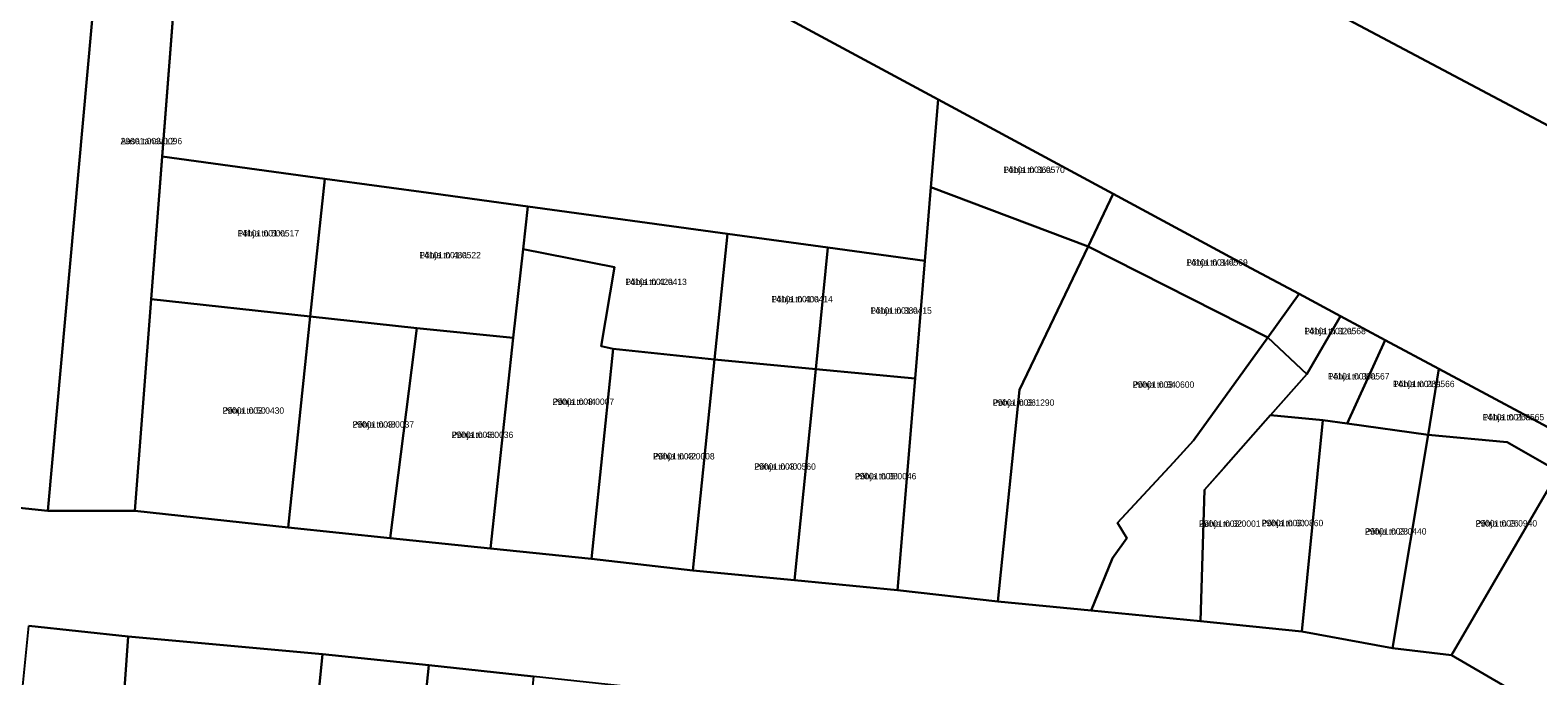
# Model space of a CAD drawing. Extents: x 566437 to 602312, y 6556921 to 6586574.
# Drawn here: x 574798.1 to 575153.3, y 6578752.1 to 6578904.2 of the extents above; entities that cross this region are included whole.
import ezdxf

# ---------------------------------------------------------------- set-up
doc = ezdxf.new("R2010")
doc.units = 0
for name, color, linetype in [('L_AADRESS', 7, 'Continuous'), ('PIIR', 7, 'Continuous'), ('TUNNUS', 7, 'Continuous')]:
    doc.layers.add(name, color=color, linetype=linetype)

msp = doc.modelspace()

# ---------------------------------------------------------------- linework, layer by layer
at = {"layer": 'PIIR'}
for points in [[(575406, 6578752.29), (575349.07, 6578781.07), (575166.28, 6578876.15), (574957.16, 6578987.09), (574778.63, 6579082.32), (574668.12, 6579165.43), (574727.46, 6579273.88), (574787.76, 6579280.44), (574952.84, 6579188.08), (574936.46, 6579155.23), (574969.66, 6579111.18), (575001.92, 6579151.58), (575596.12, 6578784.57)], [(574957.16, 6578987.09), (575166.28, 6578876.15), (575349.07, 6578781.07), (575406, 6578752.29)], [(575434.01, 6578659.03), (575394.71, 6578682.38), (575370.11, 6578695.62), (575348.87, 6578707.01), (575306.6, 6578729.65), (575277.59, 6578745.22), (575256.34, 6578756.62), (575235.19, 6578767.96), (575192.81, 6578790.71), (575183.54, 6578795.67), (575162.18, 6578807.14), (575129.97, 6578824.42), (575117.33, 6578831.2), (575106.81, 6578836.84), (575097.03, 6578842.09), (575085.64, 6578848.2), (575053.22, 6578865.69), (575011.99, 6578887.92), (574889.69, 6578953.88)], [(574521.37, 6578820.46), (574802.33, 6578791.03), (574822.78, 6578790.98), (574858.87, 6578787.06), (574882.96, 6578784.57), (574906.58, 6578782.12), (574930.36, 6578779.69), (574954.2, 6578776.94), (574978.18, 6578774.66), (575002.44, 6578772.32), (575026.02, 6578769.62), (575048.03, 6578767.52), (575073.8, 6578765.04), (575097.67, 6578762.61), (575119.02, 6578758.61), (575132.89, 6578756.99), (575153.55, 6578744.97)], [(575163.43, 6578705.76), (575129.18, 6578725.71), (575115.93, 6578732.65), (575105.48, 6578732.67), (575092.47, 6578733.85), (575065.82, 6578736.65), (575040.73, 6578739.27), (575015.83, 6578741.61), (574991.26, 6578744.1), (574966.52, 6578746.66), (574941.51, 6578749.29), (574916.65, 6578751.96), (574892.03, 6578754.61), (574866.98, 6578757.27), (574821.21, 6578761.4), (574797.84, 6578763.92)]]:
    msp.add_lwpolyline(points, dxfattribs=at)
for points in [[(574521.37, 6578820.46), (574522.44, 6578852.36), (574541.73, 6578929.3), (574565.34, 6578981.35), (574624.74, 6579091.37), (574626.51, 6579090.72), (574656.97, 6579079.35), (574820.39, 6578991.24), (574817.86, 6578963.25), (574802.33, 6578791.03)], [(574829.25, 6578874.48), (574836.53, 6578968.92), (574817.86, 6578963.25), (574820.39, 6578991.24), (574889.69, 6578953.88), (575011.99, 6578887.92), (575010.28, 6578867.21), (575008.85, 6578849.91), (574986.04, 6578853.03), (574962.36, 6578856.26), (574915.39, 6578862.69), (574893.17, 6578865.72), (574867.57, 6578869.22)], [(574822.78, 6578790.98), (574802.33, 6578791.03), (574817.86, 6578963.25), (574836.53, 6578968.92), (574826.66, 6578840.83)], [(575010.28, 6578867.21), (575011.99, 6578887.92), (575053.22, 6578865.69), (575047.3, 6578853.29)], [(574829.25, 6578874.48), (574867.57, 6578869.22), (574864.12, 6578836.78), (574826.66, 6578840.83)], [(574867.57, 6578869.22), (574893.17, 6578865.72), (574915.39, 6578862.69), (574914.22, 6578852.64), (574911.88, 6578831.76), (574889.23, 6578834.06), (574864.12, 6578836.78)], [(575047.3, 6578853.29), (575031.16, 6578819.48), (575026.02, 6578769.62), (575002.44, 6578772.32), (575006.56, 6578822.18), (575008.85, 6578849.91), (575010.28, 6578867.21)], [(575047.3, 6578853.29), (575053.22, 6578865.69), (575085.64, 6578848.2), (575097.03, 6578842.09), (575089.63, 6578831.83)], [(574915.39, 6578862.69), (574962.36, 6578856.26), (574959.34, 6578826.68), (574935.47, 6578829.14), (574932.63, 6578829.77), (574935.79, 6578848.44), (574914.22, 6578852.64)], [(574962.36, 6578856.26), (574986.04, 6578853.03), (574983.17, 6578824.41), (574959.34, 6578826.68)], [(574935.79, 6578848.44), (574932.63, 6578829.77), (574935.47, 6578829.14), (574930.36, 6578779.69), (574906.58, 6578782.12), (574911.88, 6578831.76), (574914.22, 6578852.64)], [(575008.85, 6578849.91), (575006.56, 6578822.18), (574983.17, 6578824.41), (574986.04, 6578853.03)], [(575031.16, 6578819.48), (575047.3, 6578853.29), (575089.63, 6578831.83), (575072.12, 6578807.56), (575067.47, 6578802.37), (575054.27, 6578788.21), (575056.48, 6578784.53), (575053.08, 6578779.84), (575048.03, 6578767.52), (575026.02, 6578769.62)], [(575089.63, 6578831.83), (575097.03, 6578842.09), (575106.81, 6578836.84), (575098.85, 6578823.17)], [(574864.12, 6578836.78), (574858.87, 6578787.06), (574822.78, 6578790.98), (574826.66, 6578840.83)], [(574864.12, 6578836.78), (574889.23, 6578834.06), (574882.96, 6578784.57), (574858.87, 6578787.06)], [(575090.29, 6578813.52), (575098.85, 6578823.17), (575106.81, 6578836.84), (575117.33, 6578831.2), (575108.32, 6578811.56), (575102.63, 6578812.36)], [(574889.23, 6578834.06), (574911.88, 6578831.76), (574906.58, 6578782.12), (574882.96, 6578784.57)], [(575053.08, 6578779.84), (575056.48, 6578784.53), (575054.27, 6578788.21), (575067.47, 6578802.37), (575072.12, 6578807.56), (575089.63, 6578831.83), (575098.85, 6578823.17), (575090.29, 6578813.52), (575079.21, 6578801), (575074.71, 6578795.96), (575073.8, 6578765.04), (575048.03, 6578767.52)], [(575108.32, 6578811.56), (575117.33, 6578831.2), (575129.97, 6578824.42), (575127.39, 6578808.89)], [(574930.36, 6578779.69), (574935.47, 6578829.14), (574959.34, 6578826.68), (574954.2, 6578776.94)], [(574959.34, 6578826.68), (574983.17, 6578824.41), (574978.18, 6578774.66), (574954.2, 6578776.94)], [(574983.17, 6578824.41), (575006.56, 6578822.18), (575002.44, 6578772.32), (574978.18, 6578774.66)], [(575127.39, 6578808.89), (575129.97, 6578824.42), (575162.18, 6578807.14), (575158.14, 6578800.23), (575146.02, 6578807.18)], [(575097.67, 6578762.61), (575073.8, 6578765.04), (575074.71, 6578795.96), (575090.29, 6578813.52), (575102.63, 6578812.36)], [(575127.39, 6578808.89), (575119.02, 6578758.61), (575097.67, 6578762.61), (575102.63, 6578812.36), (575108.32, 6578811.56)], [(575127.39, 6578808.89), (575146.02, 6578807.18), (575158.14, 6578800.23), (575132.89, 6578756.99), (575119.02, 6578758.61)], [(575132.89, 6578756.99), (575158.14, 6578800.23), (575178.98, 6578787.96), (575156.52, 6578749.99), (575153.55, 6578744.97)], [(574797.84, 6578763.92), (574821.21, 6578761.4), (574817.87, 6578713.42), (574817.76, 6578684.21), (574815.04, 6578684.1), (574813.47, 6578657.09), (574808.76, 6578630.6), (574806.63, 6578604.36), (574804.71, 6578578.11), (574807.07, 6578578.37), (574806.47, 6578553.64), (574805.57, 6578545.21), (574775.61, 6578543.46), (574777.76, 6578566.28), (574780.61, 6578596.15), (574783.62, 6578626.03), (574787.49, 6578655.77), (574790.41, 6578686.15), (574793.02, 6578716.04)], [(574866.98, 6578757.27), (574862.25, 6578709.62), (574837.07, 6578711.62), (574817.87, 6578713.42), (574821.21, 6578761.4)], [(574892.03, 6578754.61), (574887.09, 6578706.89), (574862.25, 6578709.62), (574866.98, 6578757.27)], [(574916.65, 6578751.96), (574910.16, 6578688.23), (574885.05, 6578686.8), (574887.09, 6578706.89), (574892.03, 6578754.61)]]:
    msp.add_lwpolyline(points, close=True, dxfattribs=at)

# ---------------------------------------------------------------- texts
at = {"layer": 'L_AADRESS'}
for s, p in [('Aasa tänav L2', (574819.43, 6578877.36)), ('Põhja tn 36a', (575027.33, 6578870.61)), ('Põhja tn 50a', (574846.96, 6578855.63)), ('Põhja tn 48a', (574889.78, 6578850.49)), ('Põhja tn 34a', (575070.42, 6578848.76)), ('Põhja tn 42a', (574938.29, 6578844.2)), ('Põhja tn 40a', (574972.69, 6578840.13)), ('Põhja tn 38a', (574996.01, 6578837.43)), ('Põhja tn 32a', (575098.22, 6578832.61)), ('Põhja tn 34', (575057.83, 6578819.99)), ('Põhja tn 30a', (575103.81, 6578821.94)), ('Põhja tn 28a', (575119.14, 6578820.14)), ('Põhja tn 44', (574921.18, 6578815.96)), ('Põhja tn 36', (575024.87, 6578815.74)), ('Põhja tn 50', (574843.45, 6578813.87)), ('Põhja tn 26a', (575140.24, 6578812.33)), ('Põhja tn 48', (574874.05, 6578810.6)), ('Põhja tn 46', (574897.42, 6578808.15)), ('Põhja tn 42', (574944.85, 6578803.1)), ('Põhja tn 40', (574968.69, 6578800.68)), ('Põhja tn 38', (574992.37, 6578798.41)), ('Põhja tn 32', (575073.44, 6578787.23)), ('Põhja tn 30', (575088.21, 6578787.38)), ('Põhja tn 26', (575138.58, 6578787.3)), ('Põhja tn 28', (575112.53, 6578785.4))]:
    msp.add_text(s, height=1.5, dxfattribs=at).set_placement(p)
at = {"layer": 'TUNNUS'}
for s, p in [('29001:003:0096', (574819.43, 6578877.36)), ('14101:001:0570', (575027.33, 6578870.61)), ('14101:001:0517', (574846.96, 6578855.63)), ('14101:001:0522', (574889.78, 6578850.49)), ('14101:001:0569', (575070.42, 6578848.76)), ('14101:001:0413', (574938.29, 6578844.2)), ('14101:001:0414', (574972.69, 6578840.13)), ('14101:001:0415', (574996.01, 6578837.43)), ('14101:001:0568', (575098.22, 6578832.61)), ('29001:003:0600', (575057.83, 6578819.99)), ('14101:001:0567', (575103.81, 6578821.94)), ('14101:001:0566', (575119.14, 6578820.14)), ('29001:003:0007', (574921.18, 6578815.96)), ('29001:003:1290', (575024.87, 6578815.74)), ('29001:003:0430', (574843.45, 6578813.87)), ('14101:001:0565', (575140.24, 6578812.33)), ('29001:003:0037', (574874.05, 6578810.6)), ('29001:003:0036', (574897.42, 6578808.15)), ('29001:003:0008', (574944.85, 6578803.1)), ('29001:003:0560', (574968.69, 6578800.68)), ('29001:003:0046', (574992.37, 6578798.41)), ('29001:003:0001', (575073.44, 6578787.23)), ('29001:003:0860', (575088.21, 6578787.38)), ('29001:003:0940', (575138.58, 6578787.3)), ('29001:003:0440', (575112.53, 6578785.4))]:
    msp.add_text(s, height=1.5, dxfattribs=at).set_placement(p)

doc.saveas('drawing.dxf')
